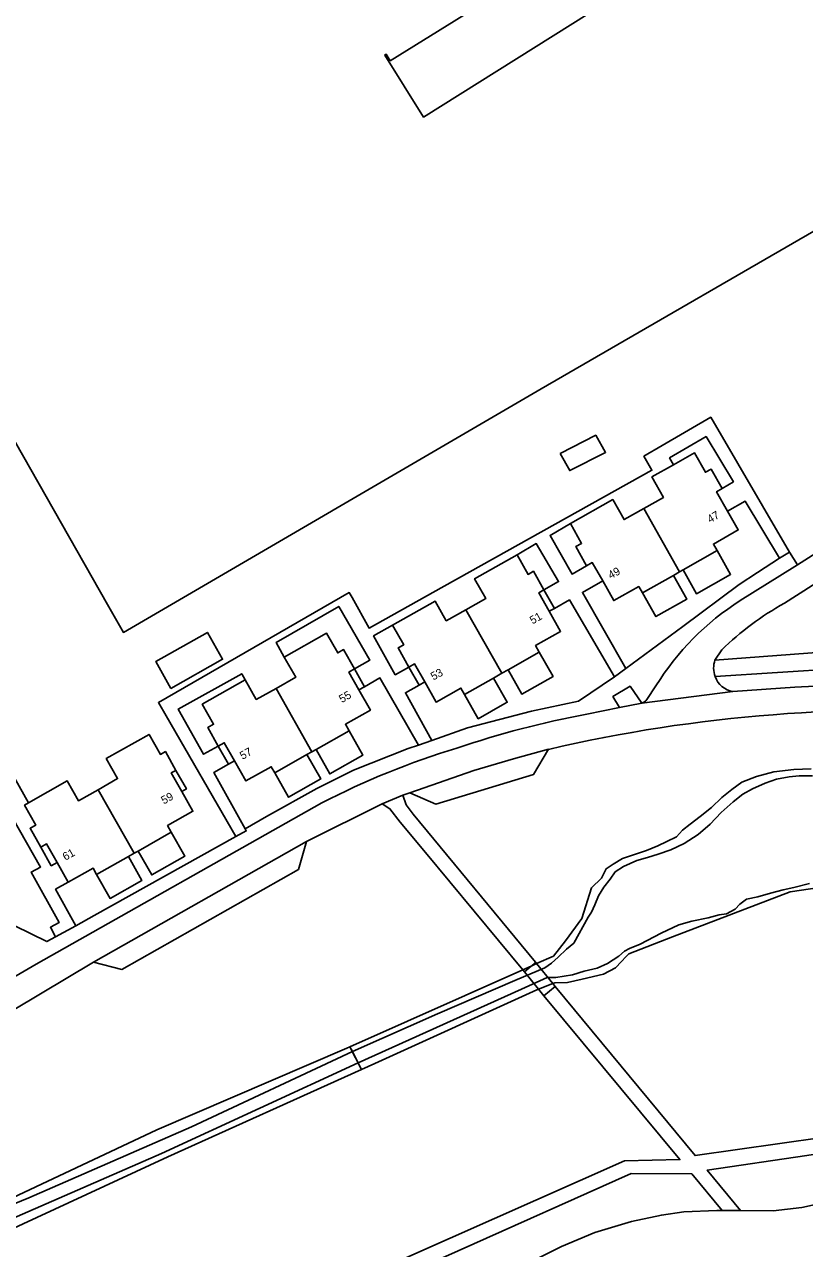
# Model space of a CAD drawing. Extents: x 158132 to 159658, y 385257 to 387209.
# Drawn here: x 158829.4 to 158926.9, y 386556 to 386709 of the extents above; entities that cross this region are included whole.
import ezdxf

# ---------------------------------------------------------------- set-up
doc = ezdxf.new("R2010")
doc.units = 0
for name, color, linetype in [('IMGEO_Dek', 7, 'Continuous'), ('IMGEO_Gemengd_bos', 7, 'Continuous'), ('IMGEO_Groenvoorziening', 7, 'Continuous'), ('IMGEO_Oever', 7, 'Continuous'), ('IMGEO_Open_loods', 7, 'Continuous'), ('IMGEO_Pand', 7, 'Continuous'), ('IMGEO_Pand_nummerreeks', 7, 'Continuous'), ('IMGEO_Parkeervlak_open', 7, 'Continuous'), ('IMGEO_Rijbaan_lokaal_gesloten', 7, 'Continuous'), ('IMGEO_Stuw', 7, 'Continuous'), ('IMGEO_Voetpad_open', 7, 'Continuous'), ('IMGEO_Waterloop', 7, 'Continuous')]:
    doc.layers.add(name, color=color, linetype=linetype)

msp = doc.modelspace()

# ---------------------------------------------------------------- linework, layer by layer
at = {"layer": 'IMGEO_Dek'}
msp.add_lwpolyline([(158893.42, 386591.59), (158893.28, 386591.76), (158892.74, 386591.28), (158891.9, 386590.55), (158893.66, 386588.4), (158894.35, 386587.56), (158895.75, 386588.72), (158895.45, 386589.1)], close=True, dxfattribs=at)
at = {"layer": 'IMGEO_Gemengd_bos'}
msp.add_lwpolyline([(158952.31, 386658.15), (158934.18, 386686.67), (158894, 386663.42), (158841.79, 386632.99), (158839.81, 386636.46), (158826.35, 386660.11), (158809.51, 386650.52), (158797.01, 386643.41)], dxfattribs=at)
at = {"layer": 'IMGEO_Groenvoorziening'}
for points in [[(158927.73, 386615.93), (158925.57, 386615.84), (158923.06, 386615.55), (158920.91, 386614.98), (158919.08, 386614.26), (158917.83, 386613.37), (158916.57, 386612.37), (158915.29, 386611.12), (158913.85, 386610), (158912.61, 386609.03), (158911.68, 386608.27), (158910.91, 386607.46), (158909.71, 386606.85), (158908.6, 386606.32), (158907.15, 386605.72), (158904.16, 386604.73), (158903, 386604.04), (158902.12, 386603.45), (158901.83, 386602.85), (158901.55, 386602.26), (158900.3, 386601.08), (158899.07, 386597.22), (158897.04, 386594.45), (158895.52, 386592.52), (158893.42, 386591.59)], [(158895.45, 386589.1), (158895.7, 386589.2), (158897.31, 386589.25), (158899.14, 386589.66), (158901.81, 386590.29), (158903.27, 386591.08), (158904.05, 386591.87), (158904.56, 386592.44), (158904.95, 386592.82), (158910.42, 386594.96), (158925.12, 386600.55), (158932.74, 386601.71)], [(158870.09, 386581.19), (158891.69, 386590.81)], [(158893.66, 386588.4), (158895.45, 386589.1)], [(158895.45, 386589.1), (158895.75, 386588.72)], [(158893.66, 386588.4), (158893.44, 386588.31), (158873.2, 386579.11), (158871.54, 386578.36)], [(158894.35, 386587.56), (158893.66, 386588.4)], [(158871.54, 386578.36), (158847.34, 386567.44), (158827.03, 386558.04), (158825.5, 386558.41), (158824.82, 386559.92), (158825.76, 386561.3), (158845.97, 386570.81), (158869.71, 386581.02), (158870.09, 386581.19)]]:
    msp.add_lwpolyline(points, dxfattribs=at)
at = {"layer": 'IMGEO_Oever'}
for points in [[(158870.4, 386580.59), (158870.09, 386581.19)], [(158871.54, 386578.36), (158871.12, 386579.19)]]:
    msp.add_lwpolyline(points, dxfattribs=at)
at = {"layer": 'IMGEO_Open_loods'}
msp.add_lwpolyline([(158900.1, 386710.42), (158895.26, 386718.18), (158895.09, 386718.08), (158895.64, 386717.2), (158875.13, 386704.45), (158874.63, 386705.26), (158874.46, 386705.16), (158879.3, 386697.4), (158900.1, 386710.42)], dxfattribs=at)
at = {"layer": 'IMGEO_Pand'}
for points in [[(158896.37, 386655.36), (158897.58, 386653.21), (158902.04, 386655.49), (158900.83, 386657.64), (158896.37, 386655.36)], [(158910.52, 386653.95), (158913.16, 386655.45), (158914.53, 386653.01), (158915.23, 386653.41), (158916.61, 386650.97)], [(158906.82, 386648.48), (158909.28, 386649.87), (158907.83, 386652.43), (158910.52, 386653.95)], [(158916.61, 386650.97), (158915.92, 386650.58), (158917.3, 386648.14)], [(158897.65, 386646.61), (158902.94, 386649.6), (158904.36, 386647.09), (158906.82, 386648.48)], [(158911.3, 386640.55), (158906.82, 386648.48)], [(158917.3, 386648.14), (158918.62, 386645.8), (158915.52, 386644.04), (158915.99, 386643.21)], [(158899.68, 386641.32), (158898.32, 386643.71), (158899.06, 386644.12), (158897.65, 386646.61)], [(158884.6, 386635.83), (158887.07, 386637.23), (158885.68, 386639.69), (158890.99, 386642.69)], [(158890.99, 386642.69), (158892.37, 386640.25), (158893.04, 386640.63), (158894.35, 386638.3)], [(158915.99, 386643.21), (158911.73, 386640.8)], [(158901.69, 386639.42), (158900.39, 386641.72), (158899.68, 386641.32)], [(158911.73, 386640.8), (158911.3, 386640.55)], [(158906.66, 386637.93), (158906.2, 386638.73), (158903.08, 386636.96), (158901.69, 386639.42)], [(158910.53, 386640.12), (158906.66, 386637.93)], [(158911.3, 386640.55), (158910.53, 386640.12)], [(158894.99, 386635.63), (158893.69, 386637.93), (158894.35, 386638.3)], [(158875.43, 386633.9), (158880.74, 386636.9), (158882.13, 386634.44), (158884.6, 386635.83)], [(158884.6, 386635.83), (158889.1, 386627.88)], [(158894.99, 386635.63), (158896.42, 386633.11), (158893.3, 386631.35), (158893.76, 386630.52)], [(158877.48, 386628.66), (158876.12, 386631.05), (158876.82, 386631.45), (158875.43, 386633.9)], [(158847.73, 386625.97), (158854.19, 386629.63), (158852.28, 386633), (158845.82, 386629.34), (158847.73, 386625.97)], [(158861.9, 386629.89), (158867.19, 386632.88), (158868.58, 386630.42), (158869.31, 386630.84), (158870.68, 386628.42)], [(158893.76, 386630.52), (158889.86, 386628.32)], [(158860.86, 386626), (158863.32, 386627.39), (158861.9, 386629.89)], [(158877.48, 386628.66), (158878.18, 386629.06), (158879.46, 386626.8)], [(158853.65, 386618.79), (158852.34, 386621.11), (158853.06, 386621.52), (158851.65, 386624.01), (158857.02, 386627.05)], [(158857.02, 386627.05), (158858.4, 386624.61), (158860.86, 386626)], [(158871.23, 386625.82), (158869.98, 386628.03), (158870.68, 386628.42)], [(158888.06, 386627.29), (158884.42, 386625.24)], [(158889.1, 386627.88), (158888.06, 386627.29)], [(158889.86, 386628.32), (158889.1, 386627.88)], [(158865.35, 386618.07), (158860.86, 386626)], [(158871.23, 386625.82), (158872.66, 386623.29), (158869.53, 386621.52), (158869.99, 386620.7)], [(158884.42, 386625.24), (158883.96, 386626.04), (158880.87, 386624.29), (158879.46, 386626.8)], [(158848.36, 386615.75), (158847.03, 386618.1), (158846.41, 386617.75), (158844.99, 386620.25), (158839.65, 386617.23), (158841.07, 386614.72), (158838.62, 386613.33)], [(158869.99, 386620.7), (158865.86, 386618.36)], [(158853.65, 386618.79), (158854.39, 386619.21), (158855.67, 386616.94)], [(158865.35, 386618.07), (158864.73, 386617.72)], [(158865.86, 386618.36), (158865.35, 386618.07)], [(158860.7, 386615.44), (158860.27, 386616.21), (158857.1, 386614.42), (158855.67, 386616.94)], [(158864.73, 386617.72), (158860.7, 386615.44)], [(158849.08, 386613.11), (158847.77, 386615.42), (158848.36, 386615.75)], [(158838.62, 386613.33), (158836.17, 386611.95), (158834.77, 386614.42), (158829.92, 386611.68)], [(158843.12, 386605.38), (158838.62, 386613.33)], [(158829.92, 386611.68), (158829.43, 386611.4), (158830.84, 386608.92), (158830.13, 386608.52), (158831.47, 386606.15)], [(158847.77, 386608.01), (158847.3, 386608.84), (158850.48, 386610.64), (158849.08, 386613.11)], [(158847.77, 386608.01), (158843.64, 386605.67)], [(158831.47, 386606.15), (158832.18, 386606.55), (158833.49, 386604.23)], [(158843.12, 386605.38), (158843.64, 386605.67)], [(158833.49, 386604.23), (158834.88, 386601.77)], [(158842.42, 386604.98), (158838.44, 386602.73)], [(158842.42, 386604.98), (158843.12, 386605.38)], [(158834.88, 386601.77), (158837.99, 386603.53), (158838.44, 386602.73)]]:
    msp.add_lwpolyline(points, dxfattribs=at)
at = {"layer": 'IMGEO_Parkeervlak_open'}
for points in [[(158894.9, 386618.38), (158893.06, 386615.24), (158880.85, 386611.52), (158877.57, 386612.95)], [(158864.67, 386606.85), (158863.68, 386603.37), (158841.59, 386590.87), (158838.06, 386591.79)]]:
    msp.add_lwpolyline(points, dxfattribs=at)
at = {"layer": 'IMGEO_Rijbaan_lokaal_gesloten'}
for points in [[(158924.41, 386636.64), (159000, 386684.91), (159014.91, 386694.38)], [(158952.31, 386658.15), (158926.04, 386641.44)], [(158926.04, 386641.44), (158925.69, 386641.22), (158918.87, 386636.97)], [(158915.72, 386629.54), (158916.56, 386630.81)], [(158917.97, 386625.61), (158906.57, 386624.16)], [(158908.34, 386626.31), (158907.21, 386624.59)], [(158953.96, 386625.78), (158944.85, 386626.47), (158936.8, 386626.71), (158925.72, 386626.16), (158917.97, 386625.61)], [(158906.57, 386624.16), (158903.79, 386623.6)], [(158903.79, 386623.6), (158899.7, 386622.78)], [(158877.57, 386612.95), (158885.6, 386615.73), (158890.53, 386617.17), (158894.9, 386618.38)], [(158866.59, 386611.69), (158830.89, 386591.54), (158824.65, 386587.92), (158820.79, 386585.6), (158819.2, 386584.7), (158818.52, 386584.29)], [(158874.11, 386611.57), (158876.73, 386612.63)], [(158876.73, 386612.63), (158877.57, 386612.95)], [(158864.67, 386606.85), (158874.11, 386611.57)], [(158838.06, 386591.79), (158864.67, 386606.85)], [(158821.34, 386581.8), (158838.06, 386591.79)], [(158967.62, 386579.06), (158956.26, 386573.35), (158947.92, 386568.97), (158939.7, 386565.13), (158932.88, 386562.49), (158926.58, 386561.12), (158922.98, 386560.71), (158918.93, 386560.73)], [(158916.6, 386560.75), (158915.94, 386560.75), (158911.81, 386560.55), (158909.03, 386560.17), (158905.3, 386559.36), (158900.72, 386557.98), (158896.53, 386556.23), (158888.13, 386552.01), (158867.23, 386541.45), (158864.7, 386540.13)], [(158918.93, 386560.73), (158916.6, 386560.75)]]:
    msp.add_lwpolyline(points, dxfattribs=at)
for centre, radius, start, end in [((158936.79, 386608.75), 33.42, 122.4081, 148.3217), ((158941.93, 386604.88), 36.27, 118.8862, 134.3777), ((158918.56, 386628.55), 3.01, 160.7472, 200.8628), ((158918.38, 386628.35), 2.77, 198.3408, 261.5019), ((158906.22, 386625.39), 1.28, 285.7553, 321.1755), ((158921.4, 386506.5), 118.28, 100.5703, 108.7091), ((158937.68, 386434.2), 189.08, 85.8307, 103.0757), ((158912.82, 386521.96), 100.94, 106.9126, 117.2584)]:
    msp.add_arc(centre, radius, start, end, dxfattribs=at)
at = {"layer": 'IMGEO_Stuw'}
msp.add_lwpolyline([(158871.54, 386578.36), (158870.09, 386581.19)], dxfattribs=at)
at = {"layer": 'IMGEO_Voetpad_open'}
for points in [[(158925.02, 386643.04), (158915.19, 386659.89), (158909.13, 386656.36), (158906.85, 386655.02), (158907.83, 386653.27), (158880.44, 386637.97), (158872.5, 386633.54), (158870.37, 386637.36), (158870.01, 386637.98), (158846.17, 386624.23), (158847.13, 386622.56), (158855.83, 386607.47)], [(158910.52, 386653.95), (158910.04, 386654.8), (158914.62, 386657.47), (158918.02, 386651.83), (158916.61, 386650.97)], [(158917.3, 386648.14), (158919.5, 386649.38), (158923.8, 386642.26)], [(158899.68, 386641.32), (158897.86, 386640.29), (158895.11, 386645.11), (158897.65, 386646.61)], [(158890.99, 386642.69), (158893.39, 386644.1), (158896.18, 386639.34), (158894.35, 386638.3)], [(158923.8, 386642.26), (158921.04, 386640.5), (158918.74, 386639), (158911.71, 386633.74), (158904.56, 386628.48)], [(158915.99, 386643.21), (158917.67, 386640.24), (158913.41, 386637.83), (158911.73, 386640.8)], [(158925.02, 386643.04), (158923.8, 386642.26)], [(158926.04, 386641.44), (158925.02, 386643.04)], [(158904.56, 386628.48), (158899.16, 386637.99), (158901.69, 386639.42)], [(158910.53, 386640.12), (158912.21, 386637.15), (158908.33, 386634.96), (158906.66, 386637.93)], [(158894.35, 386638.3), (158895.65, 386636)], [(158861.9, 386629.89), (158860.87, 386631.73), (158868.71, 386636.24), (158872.57, 386629.51), (158870.68, 386628.42)], [(158895.65, 386636), (158897.52, 386637.06), (158903.15, 386627.44)], [(158895.65, 386636), (158894.99, 386635.63)], [(158877.48, 386628.66), (158875.76, 386627.7), (158873.05, 386632.56), (158875.43, 386633.9)], [(158893.76, 386630.52), (158895.48, 386627.49), (158891.58, 386625.28), (158889.86, 386628.32)], [(158951.48, 386630.23), (158943.5, 386630.7), (158936.55, 386630.88), (158931.19, 386630.68), (158915.72, 386629.54)], [(158878.75, 386626.4), (158877.48, 386628.66)], [(158904.56, 386628.48), (158903.15, 386627.44)], [(158951.59, 386628), (158943.5, 386628.53), (158936.63, 386628.64), (158931.34, 386628.47), (158915.75, 386627.48)], [(158853.65, 386618.79), (158851.8, 386617.76), (158848.65, 386623.41), (158856.58, 386627.83), (158857.02, 386627.05)], [(158870.68, 386628.42), (158871.93, 386626.21)], [(158871.93, 386626.21), (158873.84, 386627.31), (158878.67, 386618.91)], [(158903.15, 386627.44), (158898.68, 386624.38), (158892.81, 386623.14), (158884.79, 386621.05), (158880.35, 386619.5)], [(158888.06, 386627.29), (158889.77, 386624.26), (158889.46, 386624.09), (158886.13, 386622.21), (158884.42, 386625.24)], [(158871.93, 386626.21), (158871.23, 386625.82)], [(158880.35, 386619.5), (158877.03, 386625.44), (158878.75, 386626.4)], [(158879.46, 386626.8), (158878.75, 386626.4)], [(158903.79, 386623.6), (158902.97, 386624.98), (158905.11, 386626.27), (158906.57, 386624.16)], [(158829.92, 386611.68), (158824.99, 386620.4)], [(158869.99, 386620.7), (158871.72, 386617.65), (158867.58, 386615.31), (158865.86, 386618.36)], [(158880.35, 386619.5), (158878.67, 386618.91)], [(158822.65, 386619.06), (158831.43, 386603.67), (158830.27, 386603.03), (158833.74, 386596.73), (158832.66, 386596.14), (158833.32, 386594.94)], [(158854.94, 386616.53), (158853.65, 386618.79)], [(158878.67, 386618.91), (158877.39, 386618.47), (158870.56, 386615.79), (158865.97, 386613.47), (158859.68, 386609.98), (158856.99, 386608.46)], [(158856.99, 386608.46), (158853.07, 386615.48), (158854.94, 386616.53)], [(158855.67, 386616.94), (158854.94, 386616.53)], [(158864.73, 386617.72), (158866.46, 386614.67), (158862.43, 386612.39), (158860.7, 386615.44)], [(158848.36, 386615.75), (158849.67, 386613.44), (158849.08, 386613.11)], [(158893.42, 386591.59), (158893.28, 386591.76), (158878.02, 386610.26), (158877.11, 386611.46), (158876.73, 386612.63)], [(158891.69, 386590.81), (158879.56, 386605.47), (158876.37, 386609.29), (158875.1, 386610.95), (158874.11, 386611.57)], [(158855.83, 386607.47), (158838.15, 386597.61), (158835.84, 386596.33)], [(158843.64, 386605.67), (158845.33, 386602.68), (158849.46, 386605.02), (158847.77, 386608.01)], [(158856.99, 386608.46), (158857.14, 386608.19), (158855.83, 386607.47)], [(158833.32, 386594.94), (158832.23, 386594.34), (158808.08, 386606.17)], [(158833.49, 386604.23), (158832.78, 386603.83), (158831.47, 386606.15)], [(158838.44, 386602.73), (158840.13, 386599.74), (158844.11, 386601.99), (158842.42, 386604.98)], [(159006.72, 386603.53), (159001.96, 386600.31), (158988.97, 386593.69), (158966.33, 386582.33), (158953.82, 386576.29), (158948.36, 386574.23), (158942.3, 386572.55), (158934.39, 386570.62), (158913.24, 386567.6), (158895.75, 386588.72)], [(158835.84, 386596.33), (158833.32, 386600.9), (158834.88, 386601.77)], [(158835.84, 386596.33), (158833.32, 386594.94)], [(158891.69, 386590.81), (158892.74, 386591.28), (158893.42, 386591.59)], [(158895.45, 386589.1), (158893.42, 386591.59), (158892.74, 386591.28), (158891.69, 386590.81), (158891.9, 386590.55), (158893.66, 386588.4)], [(158893.66, 386588.4), (158895.45, 386589.1)], [(158893.66, 386588.4), (158894.35, 386587.56), (158895.75, 386588.72), (158895.45, 386589.1)], [(158895.75, 386588.72), (158894.35, 386587.56)], [(158833.53, 386535.48), (158904.42, 386566.95), (158911.33, 386567.1), (158894.35, 386587.56)], [(158918.93, 386560.73), (158914.76, 386565.78), (158927.21, 386567.6), (158935.28, 386568.92), (158941.52, 386570.27), (158946.54, 386571.66), (158950.62, 386573.12), (158955.64, 386575.08), (158962.89, 386578.49), (158966.89, 386580.51)], [(158864.7, 386540.13), (158862.01, 386546.04), (158905.26, 386565.37), (158912.81, 386565.3), (158916.6, 386560.75)]]:
    msp.add_lwpolyline(points, dxfattribs=at)
at = {"layer": 'IMGEO_Waterloop'}
for points in [[(158927.92, 386615.05), (158926.24, 386615.08), (158925, 386614.93), (158923.41, 386614.63), (158921.99, 386614.15), (158920.4, 386613.46), (158919.19, 386612.79), (158917.98, 386611.8), (158916.49, 386610.47), (158915.11, 386609.01), (158913.61, 386607.75), (158911.85, 386606.62), (158910.21, 386605.82), (158908.63, 386605.27), (158907.28, 386604.87), (158905.97, 386604.5), (158904.27, 386603.75), (158903.25, 386603.07), (158902.61, 386602.16), (158901.83, 386601.16), (158901.16, 386600.05), (158900.7, 386598.93), (158900.27, 386598.01), (158899.89, 386597.41), (158898.09, 386594.17), (158897.16, 386593.38), (158896.12, 386592.39), (158895.3, 386591.67), (158894.45, 386591.05), (158890.71, 386589.5), (158881.06, 386585.32), (158870.4, 386580.59)], [(158871.12, 386579.19), (158891.54, 386588.41), (158894.76, 386589.84), (158895.82, 386589.86), (158897.93, 386590.21), (158899.37, 386590.65), (158900.98, 386591.04), (158902.3, 386591.62), (158903.71, 386592.54), (158904.42, 386593.17), (158905.05, 386593.49), (158906.39, 386594.02), (158908.98, 386595.41), (158911.19, 386596.43), (158912.84, 386596.92), (158914.85, 386597.33), (158916.25, 386597.68), (158917.17, 386597.82), (158918.24, 386598.4), (158918.83, 386599.01), (158919.68, 386599.64), (158921.06, 386599.94), (158922.68, 386600.38), (158924.26, 386600.8), (158925.57, 386601.12), (158927.55, 386601.61)], [(158871.12, 386579.19), (158846.53, 386567.85), (158826.88, 386559.26), (158826.46, 386559.47), (158826.22, 386560.01), (158826.18, 386560.43), (158826.51, 386560.91), (158829.95, 386562.3), (158850.3, 386571.19), (158870.4, 386580.59)], [(158870.4, 386580.59), (158871.12, 386579.19)]]:
    msp.add_lwpolyline(points, dxfattribs=at)

# ---------------------------------------------------------------- texts
at = {"layer": 'IMGEO_Pand_nummerreeks'}
for s, rotation, p in [('47', 29.9943, (158915.1, 386646.62)), ('49', 28.625, (158902.69, 386639.63)), ('51', 29.5131, (158892.92, 386633.98)), ('53', 28.2697, (158880.52, 386626.97)), ('55', 30.0803, (158869.09, 386624.15)), ('57', 29.6792, (158856.68, 386617.06)), ('59', 28.7338, (158846.84, 386611.48)), ('61', 28.7396, (158834.53, 386604.44))]:
    msp.add_text(s, height=1, rotation=rotation, dxfattribs=at).set_placement(p)

doc.saveas('drawing.dxf')
